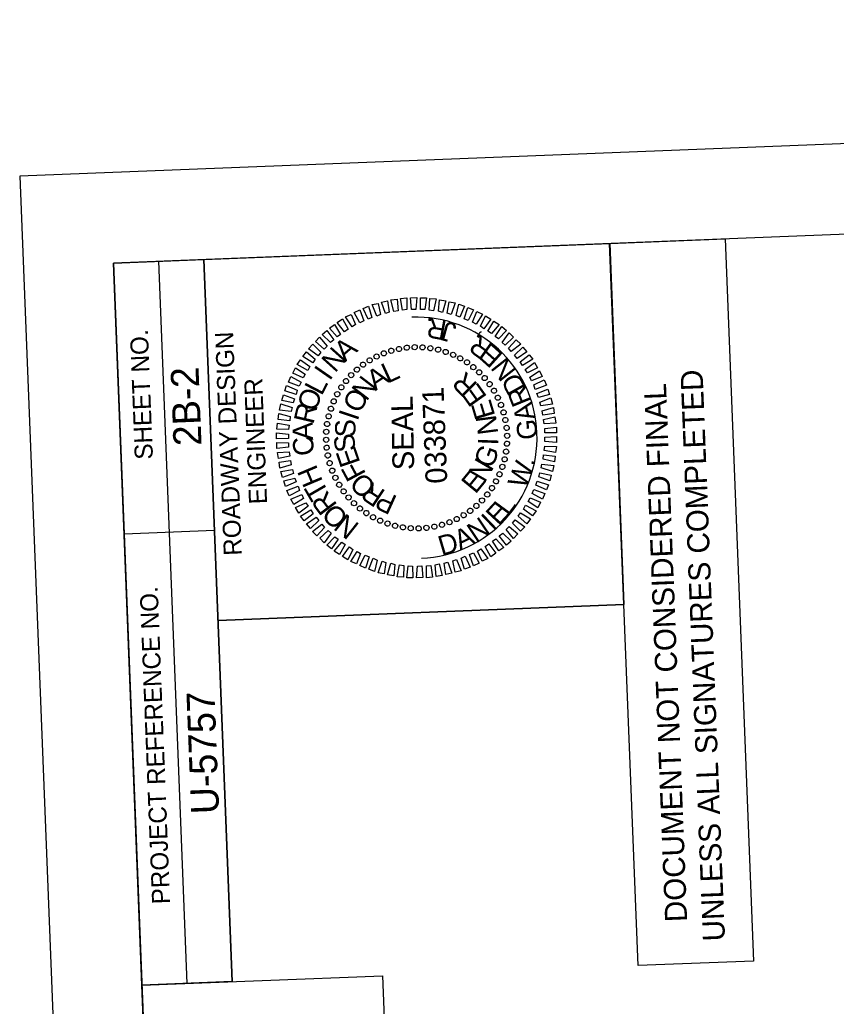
# Model space of a CAD drawing. Extents: x 1627811 to 1628977, y 762656 to 764629.
# Drawn here: x 1627810.5 to 1628036.7, y 764124.9 to 764398 of the extents above; entities that cross this region are included whole.
import ezdxf

# ---------------------------------------------------------------- set-up
doc = ezdxf.new("R2010")
doc.units = 0
for name, color, linetype in [('Old_Level_58', 7, 'Continuous'), ('Scratch_Level_0', 7, 'Continuous'), ('Sheet Data Field CELL', 7, 'Continuous'), ('Sheet Plan And Profile CELL', 7, 'Continuous'), ('Sheet Plot Border Outside CELL', 7, 'Continuous'), ('Sheet Professional Seal CELL', 7, 'Continuous'), ('Sheet Profile Grid Minor CELL', 7, 'Continuous'), ('Sheet Sticker Exception Certification CELL', 7, 'Continuous')]:
    doc.layers.add(name, color=color, linetype=linetype)

msp = doc.modelspace()

# ---------------------------------------------------------------- linework, layer by layer
at = {"layer": 'Old_Level_58'}
msp.add_lwpolyline([(1627852.24, 763930.86), (1627844.36, 764130.75), (1627911, 764133.38), (1627918.88, 763933.48)], close=True, dxfattribs=at)
at = {"layer": 'Scratch_Level_0'}
msp.add_arc((1627920.44, 764282.28), 33.36, 272.2582, 92.2582, dxfattribs=at)
at = {"layer": 'Sheet Plan And Profile CELL'}
for p, q in [((1627856.9, 764131.25), (1627849.01, 764331.14)), ((1627869.39, 764131.74), (1627861.5, 764331.63)), ((1627839.48, 764255.71), (1627864.46, 764256.69)), ((1627865.49, 764231.71), (1627977.86, 764236.14))]:
    msp.add_line(p, q, dxfattribs=at)
for points in [[(1627836.47, 764330.65), (1627895.58, 762831.81), (1628944.76, 762873.18), (1628885.66, 764372.02)], [(1627865.44, 764231.71), (1627861.5, 764331.63), (1627973.92, 764336.07), (1627977.86, 764236.14)], [(1627844.36, 764130.75), (1627836.47, 764330.65), (1627861.5, 764331.63), (1627869.39, 764131.74)]]:
    msp.add_lwpolyline(points, close=True, dxfattribs=at)
at = {"layer": 'Sheet Plot Border Outside CELL'}
msp.add_lwpolyline([(1628976.64, 762699.3), (1628909.65, 764397.98), (1627810.51, 764354.64), (1627877.49, 762655.96)], close=True, dxfattribs=at)
at = {"layer": 'Sheet Professional Seal CELL'}
for p, q in [((1627913.38, 764306.37), (1627913.38, 764306.37)), ((1627915.57, 764306.85), (1627915.57, 764306.85)), ((1627917.7, 764307.24), (1627917.7, 764307.24)), ((1627919.9, 764307.37), (1627919.9, 764307.37)), ((1627922.1, 764307.31), (1627922.1, 764307.31)), ((1627924.27, 764307.05), (1627924.27, 764307.05)), ((1627926.38, 764306.68), (1627926.38, 764306.68)), ((1627928.51, 764306.06), (1627928.51, 764306.06)), ((1627907.43, 764303.73), (1627907.43, 764303.73)), ((1627909.34, 764304.81), (1627909.34, 764304.81)), ((1627911.31, 764305.68), (1627911.31, 764305.68)), ((1627930.54, 764305.24), (1627930.54, 764305.24)), ((1627932.53, 764304.32), (1627932.53, 764304.32)), ((1627903.88, 764301.19), (1627903.88, 764301.19)), ((1627905.58, 764302.51), (1627905.58, 764302.51)), ((1627934.38, 764303.14), (1627934.38, 764303.14)), ((1627936.18, 764301.86), (1627936.18, 764301.86)), ((1627900.85, 764298.02), (1627900.85, 764298.02)), ((1627902.29, 764299.62), (1627902.29, 764299.62)), ((1627937.79, 764300.42), (1627937.79, 764300.42)), ((1627939.35, 764298.83), (1627939.35, 764298.83)), ((1627899.57, 764296.21), (1627899.57, 764296.21)), ((1627940.67, 764297.13), (1627940.67, 764297.13)), ((1627941.89, 764295.28), (1627941.89, 764295.28)), ((1627898.4, 764294.37), (1627898.4, 764294.37)), ((1627942.97, 764293.37), (1627942.97, 764293.37)), ((1627896.65, 764290.34), (1627896.65, 764290.34)), ((1627897.47, 764292.38), (1627897.47, 764292.38)), ((1627943.85, 764291.4), (1627943.85, 764291.4)), ((1627896.04, 764288.22), (1627896.04, 764288.22)), ((1627944.53, 764289.33), (1627944.53, 764289.33)), ((1627945.02, 764287.15), (1627945.02, 764287.15)), ((1627895.67, 764286.1), (1627895.67, 764286.1)), ((1627945.4, 764285.01), (1627945.4, 764285.01)), ((1627895.34, 764281.74), (1627895.34, 764281.74)), ((1627895.4, 764283.94), (1627895.4, 764283.94)), ((1627920.44, 764282.28), (1627920.44, 764282.28)), ((1627945.54, 764282.81), (1627945.54, 764282.81)), ((1627895.48, 764279.54), (1627895.48, 764279.54)), ((1627945.47, 764280.61), (1627945.47, 764280.61)), ((1627895.86, 764277.4), (1627895.86, 764277.4)), ((1627944.84, 764276.33), (1627944.84, 764276.33)), ((1627945.21, 764278.45), (1627945.21, 764278.45)), ((1627896.35, 764275.22), (1627896.35, 764275.22)), ((1627944.23, 764274.21), (1627944.23, 764274.21)), ((1627897.03, 764273.15), (1627897.03, 764273.15)), ((1627897.91, 764271.18), (1627897.91, 764271.18)), ((1627943.41, 764272.17), (1627943.41, 764272.17)), ((1627898.99, 764269.27), (1627898.99, 764269.27)), ((1627941.31, 764268.34), (1627941.31, 764268.34)), ((1627942.48, 764270.18), (1627942.48, 764270.18)), ((1627900.21, 764267.42), (1627900.21, 764267.42)), ((1627901.53, 764265.72), (1627901.53, 764265.72)), ((1627940.03, 764266.53), (1627940.03, 764266.53)), ((1627903.09, 764264.13), (1627903.09, 764264.13)), ((1627904.7, 764262.69), (1627904.7, 764262.69)), ((1627937, 764263.36), (1627937, 764263.36)), ((1627938.59, 764264.93), (1627938.59, 764264.93)), ((1627906.5, 764261.41), (1627906.5, 764261.41)), ((1627908.35, 764260.23), (1627908.35, 764260.23)), ((1627931.54, 764259.75), (1627931.54, 764259.75)), ((1627933.45, 764260.82), (1627933.45, 764260.82)), ((1627935.3, 764262.05), (1627935.3, 764262.05)), ((1627910.34, 764259.31), (1627910.34, 764259.31)), ((1627912.37, 764258.49), (1627912.37, 764258.49)), ((1627914.5, 764257.87), (1627914.5, 764257.87)), ((1627916.61, 764257.51), (1627916.61, 764257.51)), ((1627918.77, 764257.24), (1627918.77, 764257.24)), ((1627920.98, 764257.18), (1627920.98, 764257.18)), ((1627923.18, 764257.31), (1627923.18, 764257.31)), ((1627925.31, 764257.7), (1627925.31, 764257.7)), ((1627927.49, 764258.18), (1627927.49, 764258.18)), ((1627929.57, 764258.87), (1627929.57, 764258.87))]:
    msp.add_line(p, q, dxfattribs=at)
for points in [[(1627911.78, 764316.66), (1627910.7, 764319.77), (1627912.39, 764320.14), (1627912.82, 764317)], [(1627914.16, 764317.21), (1627913.33, 764320.43), (1627915.02, 764320.64), (1627915.35, 764317.45)], [(1627916.54, 764317.6), (1627916.02, 764320.83), (1627917.71, 764321), (1627917.74, 764317.75)], [(1627919.04, 764317.75), (1627918.76, 764320.99), (1627920.46, 764321.06), (1627920.24, 764317.8)], [(1627921.54, 764317.8), (1627921.51, 764321.05), (1627923.17, 764321.01), (1627922.74, 764317.74)], [(1627923.95, 764317.64), (1627924.12, 764320.85), (1627925.83, 764320.72), (1627925.16, 764317.44)], [(1627926.51, 764317.34), (1627926.79, 764320.46), (1627928.5, 764320.17), (1627927.58, 764316.98)], [(1627928.94, 764316.79), (1627929.46, 764319.91), (1627931.13, 764319.63), (1627930, 764316.43)], [(1627904.72, 764314.08), (1627903.11, 764316.97), (1627904.68, 764317.68), (1627905.8, 764314.62)], [(1627907.04, 764315.07), (1627905.62, 764318.07), (1627907.14, 764318.68), (1627908.07, 764315.61)], [(1627909.4, 764315.97), (1627908.13, 764319.12), (1627909.77, 764319.48), (1627910.44, 764316.36)], [(1627931.36, 764316.13), (1627932.14, 764319.27), (1627933.72, 764318.68), (1627932.43, 764315.62)], [(1627933.6, 764315.22), (1627934.63, 764318.36), (1627936.21, 764317.67), (1627934.72, 764314.76)], [(1627935.94, 764314.31), (1627937.08, 764317.21), (1627938.65, 764316.52), (1627936.91, 764313.75)], [(1627900.47, 764311.61), (1627898.47, 764314.18), (1627899.93, 764315.19), (1627901.44, 764312.35)], [(1627902.62, 764313), (1627900.76, 764315.73), (1627902.28, 764316.44), (1627903.54, 764313.63)], [(1627938.13, 764313.2), (1627939.52, 764316.05), (1627940.96, 764315.11), (1627939.07, 764312.43)], [(1627940.19, 764311.78), (1627941.78, 764314.54), (1627943.27, 764313.65), (1627941.17, 764311.16)], [(1627896.58, 764308.66), (1627894.24, 764310.87), (1627895.55, 764311.97), (1627897.55, 764309.39)], [(1627898.47, 764310.23), (1627896.28, 764312.6), (1627897.69, 764313.6), (1627899.4, 764310.87)], [(1627942.15, 764310.35), (1627944, 764313.03), (1627945.34, 764311.98), (1627943.08, 764309.69)], [(1627894.85, 764306.84), (1627892.42, 764308.89), (1627893.57, 764310.14), (1627895.62, 764307.62)], [(1627944.12, 764308.68), (1627946.07, 764311.31), (1627947.26, 764310.1), (1627944.95, 764307.91)], [(1627945.93, 764307.1), (1627948.04, 764309.38), (1627949.29, 764308.23), (1627946.67, 764306.18)], [(1627891.7, 764303.01), (1627888.88, 764304.75), (1627889.93, 764306.09), (1627892.36, 764303.99)], [(1627893.17, 764304.97), (1627890.5, 764306.91), (1627891.65, 764308.16), (1627893.89, 764305.95)], [(1627947.56, 764305.16), (1627949.87, 764307.4), (1627950.97, 764306.1), (1627948.25, 764304.24)], [(1627890.28, 764300.9), (1627887.32, 764302.54), (1627888.31, 764303.88), (1627890.84, 764302.02)], [(1627949.13, 764303.32), (1627951.61, 764305.27), (1627952.61, 764304.01), (1627949.78, 764302.25)], [(1627889.01, 764298.9), (1627886.11, 764300.14), (1627886.9, 764301.67), (1627889.57, 764299.87)], [(1627950.47, 764301.17), (1627953.09, 764303.13), (1627953.95, 764301.61), (1627951.11, 764300.25)], [(1627951.75, 764299.07), (1627954.49, 764300.78), (1627955.25, 764299.26), (1627952.25, 764297.99)], [(1627887.95, 764296.56), (1627884.95, 764297.69), (1627885.59, 764299.27), (1627888.46, 764297.68)], [(1627952.89, 764296.92), (1627955.73, 764298.33), (1627956.39, 764296.85), (1627953.24, 764295.68)], [(1627887.09, 764294.27), (1627883.9, 764295.3), (1627884.44, 764296.72), (1627887.4, 764295.43)], [(1627953.78, 764294.5), (1627956.74, 764295.77), (1627957.25, 764294.24), (1627954.17, 764293.46)], [(1627886.28, 764291.99), (1627883.15, 764292.61), (1627883.59, 764294.18), (1627886.59, 764293.05)], [(1627954.53, 764292.13), (1627957.63, 764293.3), (1627958.05, 764291.61), (1627954.82, 764291.09)], [(1627885.73, 764289.56), (1627882.46, 764289.93), (1627882.79, 764291.65), (1627885.93, 764290.62)], [(1627955.17, 764289.75), (1627958.34, 764290.68), (1627958.55, 764289.03), (1627955.37, 764288.56)], [(1627885.28, 764286.99), (1627882.06, 764287.32), (1627882.25, 764288.98), (1627885.38, 764288.2)], [(1627955.57, 764287.36), (1627958.74, 764288.04), (1627959.01, 764286.35), (1627955.76, 764286.17)], [(1627884.97, 764284.58), (1627881.72, 764284.65), (1627881.95, 764286.31), (1627885.12, 764285.79)], [(1627955.91, 764284.88), (1627959.15, 764285.25), (1627959.17, 764283.6), (1627955.91, 764283.67)], [(1627884.92, 764282.08), (1627881.67, 764281.95), (1627881.66, 764283.6), (1627884.92, 764283.28)], [(1627955.96, 764282.48), (1627959.21, 764282.6), (1627959.22, 764280.95), (1627955.96, 764281.27)], [(1627884.96, 764279.68), (1627881.73, 764279.3), (1627881.71, 764280.95), (1627884.97, 764280.88)], [(1627955.91, 764279.97), (1627959.16, 764279.9), (1627958.93, 764278.24), (1627955.76, 764278.76)], [(1627885.31, 764277.19), (1627882.14, 764276.51), (1627881.87, 764278.2), (1627885.12, 764278.38)], [(1627955.6, 764277.56), (1627958.82, 764277.23), (1627958.63, 764275.58), (1627955.5, 764276.35)], [(1627885.71, 764274.8), (1627882.54, 764273.88), (1627882.33, 764275.52), (1627885.51, 764275.99)], [(1627886.35, 764272.42), (1627883.25, 764271.25), (1627882.83, 764272.94), (1627886.06, 764273.46)], [(1627955.15, 764274.99), (1627958.42, 764274.62), (1627958.09, 764272.9), (1627954.95, 764273.93)], [(1627887.1, 764270.05), (1627884.14, 764268.78), (1627883.63, 764270.32), (1627886.7, 764271.09)], [(1627954.6, 764272.56), (1627957.73, 764271.94), (1627957.29, 764270.37), (1627954.29, 764271.5)], [(1627887.99, 764267.64), (1627885.14, 764266.22), (1627884.49, 764267.7), (1627887.64, 764268.87)], [(1627952.93, 764267.99), (1627955.92, 764266.86), (1627955.29, 764265.29), (1627952.42, 764266.87)], [(1627953.79, 764270.28), (1627956.98, 764269.26), (1627956.44, 764267.83), (1627953.48, 764269.12)], [(1627889.13, 764265.48), (1627886.39, 764263.77), (1627885.63, 764265.29), (1627888.63, 764266.56)], [(1627951.87, 764265.65), (1627954.77, 764264.41), (1627953.98, 764262.88), (1627951.31, 764264.68)], [(1627890.41, 764263.38), (1627887.79, 764261.42), (1627886.93, 764262.94), (1627889.77, 764264.3)], [(1627950.6, 764263.65), (1627953.56, 764262.01), (1627952.57, 764260.67), (1627950.04, 764262.53)], [(1627891.75, 764261.23), (1627889.27, 764259.28), (1627888.27, 764260.54), (1627891.1, 764262.3)], [(1627893.32, 764259.39), (1627891.01, 764257.15), (1627889.9, 764258.45), (1627892.63, 764260.31)], [(1627949.18, 764261.54), (1627952, 764259.8), (1627950.95, 764258.46), (1627948.52, 764260.56)], [(1627894.95, 764257.45), (1627892.84, 764255.17), (1627891.59, 764256.32), (1627894.21, 764258.37)], [(1627946.03, 764257.71), (1627948.46, 764255.66), (1627947.31, 764254.41), (1627945.26, 764256.93)], [(1627947.7, 764259.58), (1627950.38, 764257.64), (1627949.23, 764256.39), (1627946.99, 764258.6)], [(1627896.76, 764255.87), (1627894.81, 764253.24), (1627893.62, 764254.45), (1627895.93, 764256.64)], [(1627898.73, 764254.2), (1627896.88, 764251.52), (1627895.54, 764252.57), (1627897.8, 764254.86)], [(1627942.41, 764254.32), (1627944.6, 764251.95), (1627943.19, 764250.95), (1627941.48, 764253.68)], [(1627944.3, 764255.9), (1627946.64, 764253.69), (1627945.33, 764252.58), (1627943.33, 764255.16)], [(1627900.69, 764252.77), (1627899.09, 764250.01), (1627897.61, 764250.9), (1627899.71, 764253.39)], [(1627902.74, 764251.35), (1627901.36, 764248.5), (1627899.92, 764249.44), (1627901.81, 764252.12)], [(1627938.26, 764251.55), (1627940.12, 764248.83), (1627938.6, 764248.11), (1627937.34, 764250.92)], [(1627940.41, 764252.94), (1627942.41, 764250.37), (1627940.95, 764249.36), (1627939.44, 764252.2)], [(1627904.94, 764250.24), (1627903.8, 764247.34), (1627902.22, 764248.03), (1627903.97, 764250.8)], [(1627907.28, 764249.33), (1627906.25, 764246.19), (1627904.67, 764246.88), (1627906.16, 764249.79)], [(1627909.52, 764248.42), (1627908.74, 764245.29), (1627907.16, 764245.87), (1627908.44, 764248.93)], [(1627933.84, 764249.48), (1627935.26, 764246.48), (1627933.73, 764245.87), (1627932.81, 764248.94)], [(1627936.16, 764250.47), (1627937.77, 764247.58), (1627936.2, 764246.87), (1627935.08, 764249.93)], [(1627911.94, 764247.76), (1627911.42, 764244.64), (1627909.75, 764244.93), (1627910.88, 764248.12)], [(1627914.37, 764247.21), (1627914.09, 764244.1), (1627912.38, 764244.38), (1627913.3, 764247.57)], [(1627916.93, 764246.91), (1627916.76, 764243.7), (1627915.05, 764243.83), (1627915.72, 764247.11)], [(1627919.34, 764246.75), (1627919.37, 764243.5), (1627917.71, 764243.54), (1627918.14, 764246.81)], [(1627921.84, 764246.8), (1627922.12, 764243.56), (1627920.42, 764243.49), (1627920.64, 764246.76)], [(1627924.33, 764246.95), (1627924.86, 764243.72), (1627923.17, 764243.55), (1627923.14, 764246.8)], [(1627926.72, 764247.35), (1627927.55, 764244.13), (1627925.86, 764243.91), (1627925.53, 764247.1)], [(1627929.1, 764247.89), (1627930.17, 764244.78), (1627928.49, 764244.41), (1627928.06, 764247.55)], [(1627931.48, 764248.58), (1627932.75, 764245.43), (1627931.11, 764245.07), (1627930.44, 764248.19)]]:
    msp.add_lwpolyline(points, close=True, dxfattribs=at)
for centre, major_axis in [((1627911.35, 764305.65), (-0.261, 0.671)), ((1627913.42, 764306.35), (-0.202, 0.691)), ((1627915.54, 764306.87), (-0.141, 0.706)), ((1627917.71, 764307.21), (-0.078, 0.716)), ((1627919.89, 764307.35), (-0.016, 0.72)), ((1627922.08, 764307.3), (0.047, 0.718)), ((1627924.25, 764307.06), (0.109, 0.712)), ((1627926.4, 764306.64), (0.171, 0.699)), ((1627928.5, 764306.03), (0.231, 0.682)), ((1627930.54, 764305.23), (0.29, 0.659)), ((1627905.61, 764302.5), (-0.426, 0.581)), ((1627907.43, 764303.71), (-0.374, 0.615)), ((1627909.34, 764304.77), (-0.319, 0.646)), ((1627932.5, 764304.27), (0.346, 0.631)), ((1627934.37, 764303.13), (0.4, 0.599)), ((1627903.9, 764301.13), (-0.475, 0.541)), ((1627936.13, 764301.84), (0.451, 0.562)), ((1627937.78, 764300.39), (0.498, 0.52)), ((1627900.88, 764297.97), (-0.562, 0.451)), ((1627902.32, 764299.62), (-0.52, 0.498)), ((1627939.29, 764298.81), (0.541, 0.475)), ((1627940.66, 764297.11), (0.581, 0.426)), ((1627898.45, 764294.34), (-0.631, 0.346)), ((1627899.58, 764296.21), (-0.599, 0.4)), ((1627941.88, 764295.29), (0.615, 0.374)), ((1627897.48, 764292.37), (-0.659, 0.29)), ((1627942.93, 764293.37), (0.646, 0.319)), ((1627896.69, 764290.33), (-0.682, 0.231)), ((1627943.81, 764291.37), (0.671, 0.261)), ((1627944.52, 764289.3), (0.691, 0.202)), ((1627896.08, 764288.23), (-0.699, 0.171)), ((1627945.04, 764287.17), (0.706, 0.141)), ((1627895.41, 764283.91), (-0.718, 0.047)), ((1627895.65, 764286.09), (-0.712, 0.109)), ((1627945.37, 764285.01), (0.716, 0.078)), ((1627895.37, 764281.72), (-0.72, -0.016)), ((1627945.51, 764282.83), (0.72, 0.016)), ((1627895.51, 764279.54), (-0.716, -0.078)), ((1627945.23, 764278.46), (0.712, -0.109)), ((1627945.47, 764280.64), (0.718, -0.047)), ((1627895.84, 764277.38), (-0.706, -0.141)), ((1627896.36, 764275.25), (-0.691, -0.202)), ((1627944.8, 764276.32), (0.699, -0.171)), ((1627897.07, 764273.18), (-0.671, -0.261)), ((1627944.19, 764274.22), (0.682, -0.231)), ((1627897.95, 764271.18), (-0.646, -0.319)), ((1627942.43, 764270.22), (0.631, -0.346)), ((1627943.4, 764272.18), (0.659, -0.29)), ((1627899, 764269.26), (-0.615, -0.374)), ((1627900.22, 764267.44), (-0.581, -0.426)), ((1627941.29, 764268.34), (0.599, -0.4)), ((1627901.59, 764265.74), (-0.541, -0.475)), ((1627938.56, 764264.93), (0.52, -0.498)), ((1627940, 764266.58), (0.562, -0.451)), ((1627903.1, 764264.16), (-0.498, -0.52)), ((1627904.74, 764262.71), (-0.451, -0.562)), ((1627935.27, 764262.05), (0.426, -0.581)), ((1627936.98, 764263.42), (0.475, -0.541)), ((1627906.51, 764261.42), (-0.4, -0.599)), ((1627908.38, 764260.29), (-0.346, -0.631)), ((1627910.34, 764259.32), (-0.29, -0.659)), ((1627929.53, 764258.9), (0.261, -0.671)), ((1627931.54, 764259.78), (0.319, -0.646)), ((1627933.45, 764260.84), (0.374, -0.615)), ((1627912.38, 764258.53), (-0.231, -0.682)), ((1627914.48, 764257.91), (-0.171, -0.699)), ((1627916.63, 764257.49), (-0.109, -0.712)), ((1627918.8, 764257.25), (-0.047, -0.718)), ((1627920.99, 764257.2), (0.016, -0.72)), ((1627923.17, 764257.34), (0.078, -0.716)), ((1627925.34, 764257.68), (0.141, -0.706)), ((1627927.46, 764258.2), (0.202, -0.691))]:
    msp.add_ellipse(centre, major_axis=major_axis, ratio=0.999708, dxfattribs=at)
at = {"layer": 'Sheet Sticker Exception Certification CELL'}
for p, q in [((1627973.92, 764336.07), (1628005.87, 764337.33)), ((1628005.86, 764337.33), (1628013.74, 764137.43)), ((1627981.78, 764136.17), (1627973.9, 764336.06)), ((1628013.74, 764137.43), (1627981.78, 764136.17))]:
    msp.add_line(p, q, dxfattribs=at)

# ---------------------------------------------------------------- texts
at = {"layer": 'Sheet Data Field CELL'}
for s, p in [('2B-2', (1627860.88, 764280.15)), ('U-5757   ', (1627865.76, 764178.26))]:
    msp.add_text(s, height=7.75, rotation=92.2582, dxfattribs=at).set_placement(p)
at = {"layer": 'Sheet Plan And Profile CELL'}
for s, height, p in [('SHEET NO.', 5, (1627847.42, 764276.33)), ('ROADWAY DESIGN', 5.0001, (1627872.04, 764249.74)), ('ENGINEER', 5, (1627879.03, 764263.98)), ('PROJECT REFERENCE NO.', 5.0001, (1627852.18, 764153.28))]:
    msp.add_text(s, height=height, rotation=92.2582, dxfattribs=at).set_placement(p)
at = {"layer": 'Sheet Professional Seal CELL'}
for s, height, rotation, p in [('A', 5.64, 40.8753, (1627900.65, 764303.11)), ('N', 5.64, 48.0771, (1627897.82, 764300.05)), ('I', 5.64, 55.2783, (1627896.36, 764297.84)), ('A', 5.64, 34.0185, (1627909.02, 764295.14)), ('L', 5.64, 24.659, (1627912.39, 764297.22)), ('R', 5.64, 134.7396, (1627937.62, 764297.06)), ('N', 5.64, 52.7348, (1627906.54, 764292.19)), ('O', 5.64, 69.6794, (1627892.44, 764289.23)), ('L', 5.64, 62.4791, (1627894.12, 764293.7)), ('O', 5.64, 62.0917, (1627904.67, 764288.76)), ('E', 5.64, 125.3823, (1627940.11, 764293.61)), ('SEAL', 5.998, 91.2582, (1627919.79, 764273.39)), ('E', 5.64, 106.67, (1627942.27, 764288.39)), ('R', 5.64, 76.8793, (1627891.83, 764285.85)), ('I', 5.64, 71.4478, (1627904.05, 764286.73)), ('S', 5.64, 90.1586, (1627903.52, 764282.41)), ('N', 5.64, 97.3146, (1627943.06, 764283.47)), ('A', 5.64, 91.2785, (1627891.79, 764281.65)), ('C', 5.64, 98.4781, (1627892.25, 764277.71)), ('S', 5.64, 99.5138, (1627903.71, 764278.81)), ('I', 5.64, 87.9594, (1627943.04, 764280.11)), ('E', 5.64, 108.8693, (1627904.9, 764275.41)), ('G', 5.64, 69.2484, (1627941.4, 764273.49)), ('N', 5.64, 59.8921, (1627939.3, 764269.61)), ('H', 5.64, 112.8777, (1627894.55, 764270.2)), ('F', 5.64, 118.2252, (1627906.52, 764272.27)), ('E', 5.64, 50.5351, (1627936.72, 764266.5)), ('O', 5.64, 136.9394, (1627909.6, 764269.09)), ('T', 5.64, 120.078, (1627896.32, 764267.01)), ('R', 5.64, 146.2978, (1627912.12, 764267.44)), ('R', 5.64, 127.2787, (1627898.65, 764263.7)), ('P', 5.64, 155.6571, (1627915.38, 764265.96)), ('O', 5.64, 134.4799, (1627901.89, 764260.38)), ('N', 5.64, 141.6817, (1627904.88, 764258.19))]:
    msp.add_text(s, height=height, rotation=rotation, dxfattribs=at).set_placement(p)
at = {"layer": 'Sheet Profile Grid Minor CELL'}
for s, height, rotation, p in [('R', 5.5, 169.6122, (1627929.07, 764314.61)), ('.', 5.5, 176.5387, (1627925.11, 764315.42)), ('J', 5.5, 164.7437, (1627931.79, 764313.76)), (',', 5.5, 151.5634, (1627938.67, 764310.35)), ('R', 5.5, 144.637, (1627941.92, 764307.94)), ('E', 5.5, 138.054, (1627944.72, 764305.31)), ('N', 5.5, 128.1223, (1627948.33, 764300.78)), ('D', 5.5, 118.9777, (1627950.92, 764296.11)), ('033871', 5.998, 92.2582, (1627928.95, 764269.7)), ('R', 5.5, 112.0512, (1627952.36, 764292.33)), ('A', 5.5, 103.8654, (1627953.47, 764287.69)), ('G', 5.5, 93.9337, (1627953.91, 764281.91)), ('W', 5.5, 69.1473, (1627950.67, 764267.91)), ('.', 5.5, 80.7534, (1627952.94, 764274.29)), ('E', 5.5, 47.309, (1627943.16, 764257.7)), ('L', 5.5, 53.892, (1627945.83, 764260.46)), ('N', 5.5, 33.8568, (1627936.82, 764253.09)), ('I', 5.5, 43.7885, (1627941.61, 764256.35)), ('A', 5.5, 25.671, (1627932.49, 764251.05)), ('D', 5.5, 16.5264, (1627927.38, 764249.53))]:
    msp.add_text(s, height=height, rotation=rotation, dxfattribs=at).set_placement(p)
at = {"layer": 'Sheet Sticker Exception Certification CELL'}
for s, p in [('UNLESS ALL SIGNATURES COMPLETED', (1628005.87, 764143.02)), ('DOCUMENT NOT CONSIDERED FINAL', (1627995.39, 764148.34))]:
    msp.add_text(s, height=6.124, rotation=92.2582, dxfattribs=at).set_placement(p)

doc.saveas('drawing.dxf')
